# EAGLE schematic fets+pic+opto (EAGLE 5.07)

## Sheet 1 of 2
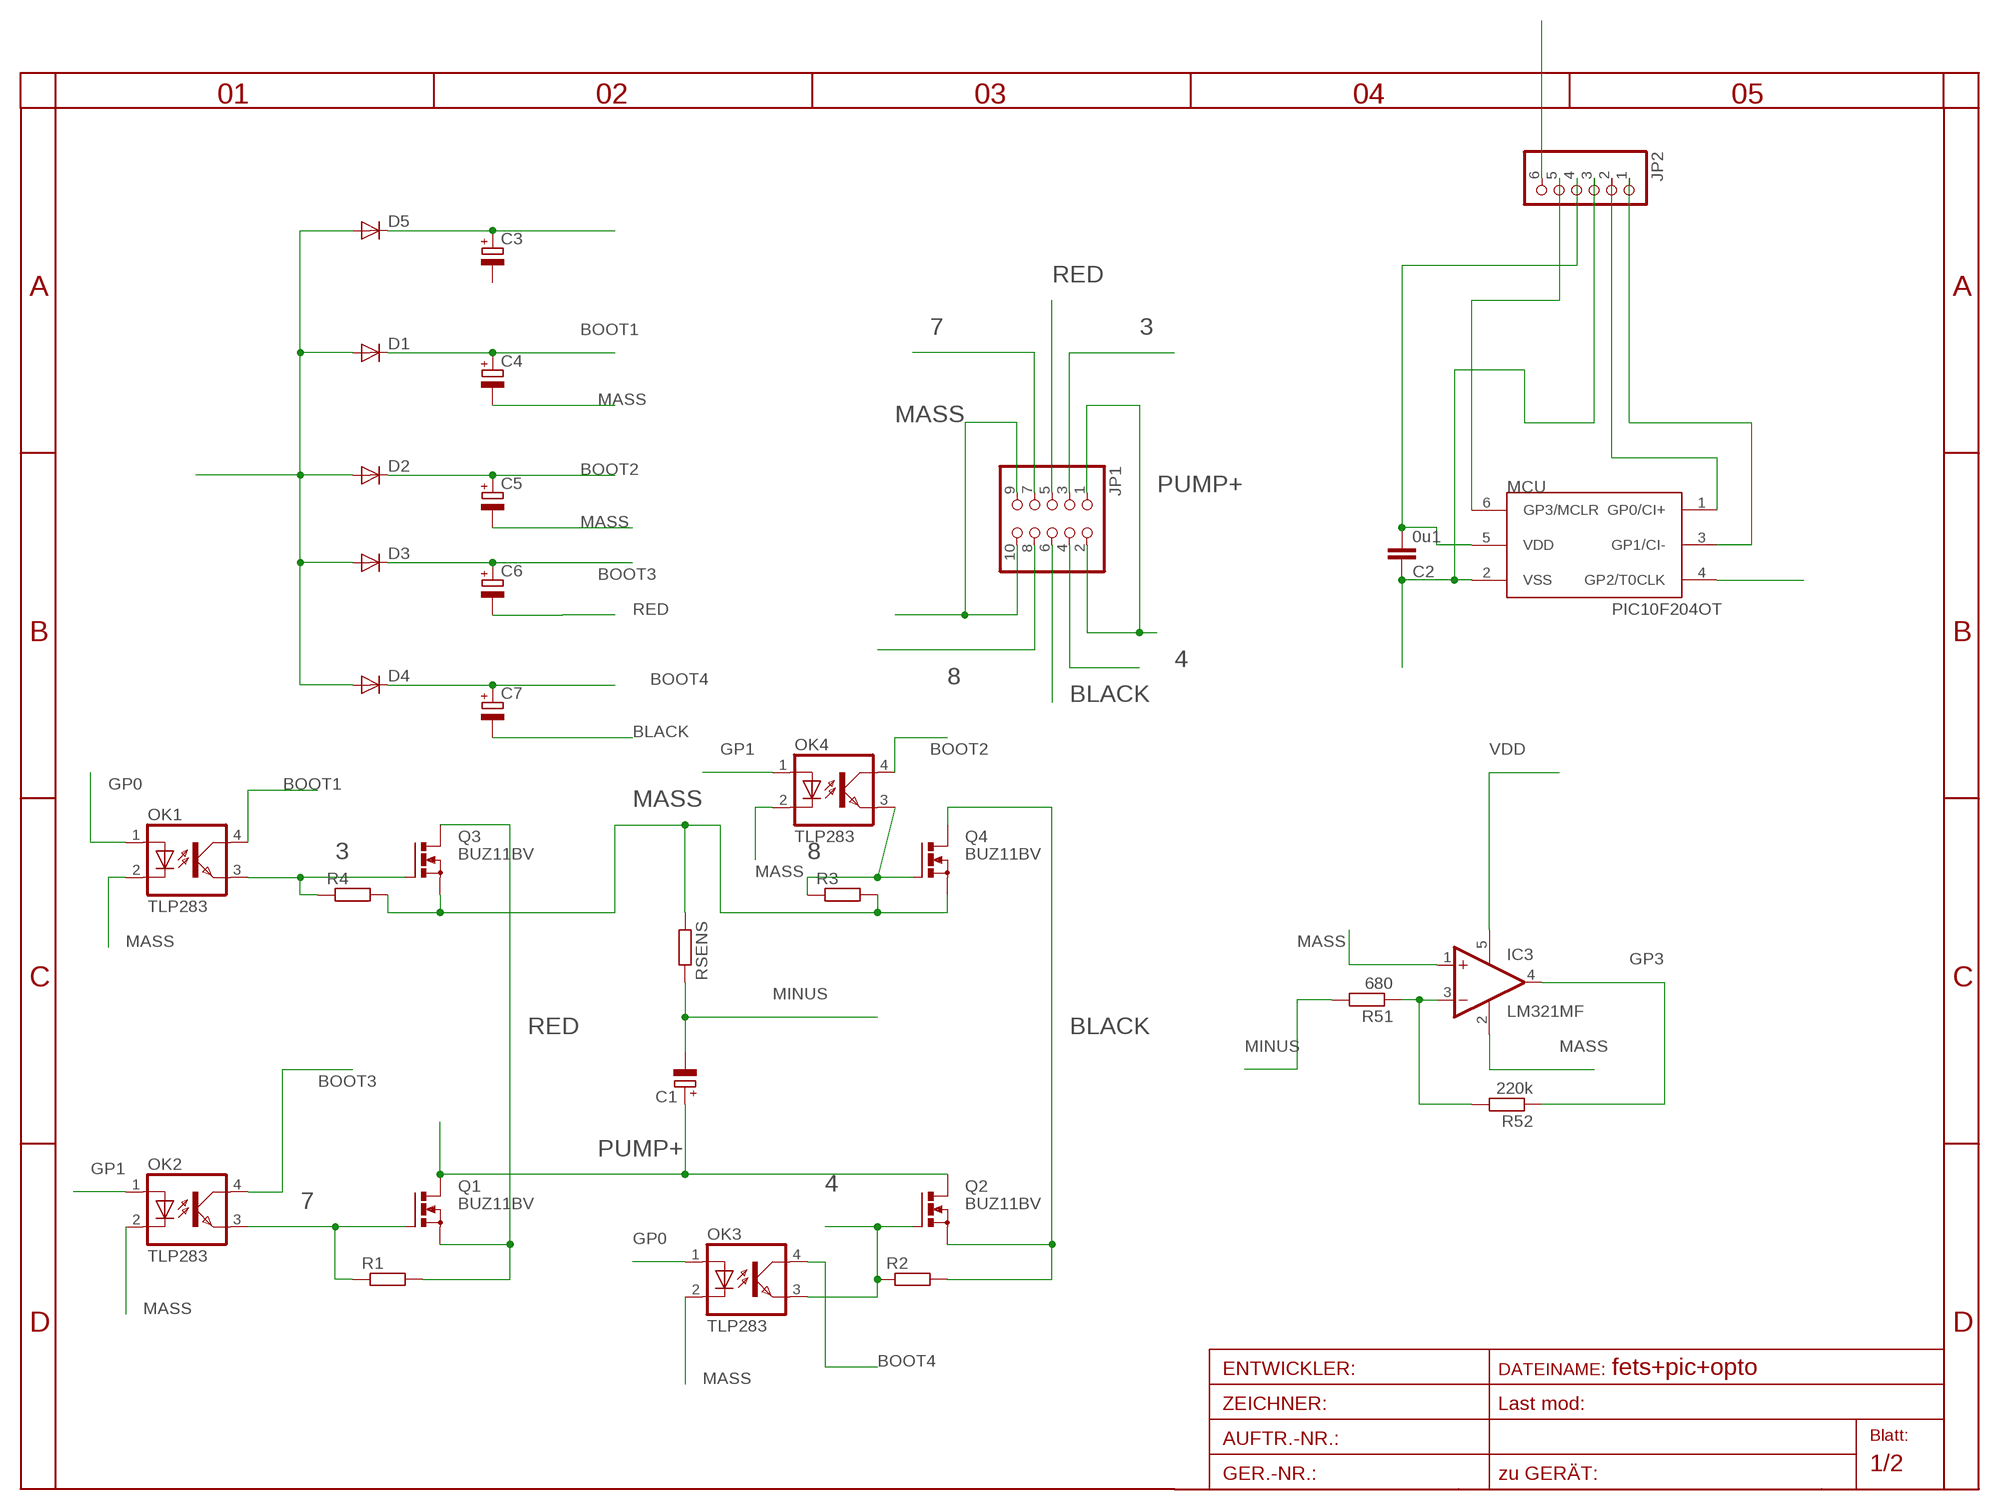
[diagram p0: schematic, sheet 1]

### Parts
C1  CPOL-EUE5-13  [E5-13]
C2  0u1  C-EUC1206  [C1206]
C3  CPOL-EUE2.5-7  [E2,5-7]
C4  CPOL-EUE2.5-7  [E2,5-7]
C5  CPOL-EUE2.5-7  [E2,5-7]
C6  CPOL-EUE2.5-7  [E2,5-7]
C7  CPOL-EUE2.5-7  [E2,5-7]
D1  DIODE-SMA-DO214  [SMA-DO214AC]
D2  DIODE-SMA-DO214  [SMA-DO214AC]
D3  DIODE-SMA-DO214  [SMA-DO214AC]
D4  DIODE-SMA-DO214  [SMA-DO214AC]
D5  DIODE-SMA-DO214  [SMA-DO214AC]
IC3  LM321MF  [SOT23-5]
JP1  PINHD-2X5  [2X05]
JP2  PINHD-1X6  [1X06BOX]
MCU  PIC10F204OT  [SOT23-6]
OK1  TLP283  [MINI-FLAT-4]
OK2  TLP283  [MINI-FLAT-4]
OK3  TLP283  [MINI-FLAT-4]
OK4  TLP283  [MINI-FLAT-4]
Q1  BUZ11BV  [TO220BV]
Q2  BUZ11BV  [TO220BV]
Q3  BUZ11BV  [TO220BV]
Q4  BUZ11BV  [TO220BV]
R1  R-EU_R1206  [R1206]
R2  R-EU_R1206  [R1206]
R3  R-EU_R1206  [R1206]
R4  R-EU_R1206  [R1206]
R51  680  R-EU_0207/10  [0207/10]
R52  220k  R-EU_0207/10  [0207/10]
RSENS  R-EU_0207/10  [0207/10]

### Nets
3: JP1.3 OK1.3(EMIT) Q3.G R4.1
4: JP1.4 OK3.3(EMIT) Q2.G R2.1
7: JP1.7 OK2.3(EMIT) Q1.G R1.1
8: JP1.8 OK4.3(EMIT) Q4.G R3.1
BATT+: JP2.6
BLACK: C7.- JP1.6 Q2.S Q4.D R2.2
BOOT1: C4.+ D1.K(C) OK1.4(COL)
BOOT2: C5.+ D2.K(C) OK4.4(COL)
BOOT3: C6.+ D3.K(C) OK2.4(COL)
BOOT4: C7.+ D4.K(C) OK3.4(COL)
GP0: JP2.2 MCU.1(GP0/CI+) OK1.1(A) OK3.1(A)
GP1: JP2.1 MCU.3(GP1/CI-) OK2.1(A) OK4.1(A)
GP2: MCU.4(GP2/T0CLK)
GP3: IC3.4(OUT) JP2.5 MCU.6(GP3/MCLR) R52.1
MASS: C2.1 C4.- C5.- IC3.1(+IN) IC3.2(V-) JP1.9 JP1.10 JP2.3 MCU.2(VSS) OK1.2(C) OK2.2(C) OK3.2(C) OK4.2(C) Q3.S Q4.S R3.2 R4.2 RSENS.1
MINUS: C1.- R51.2 RSENS.2
N$1: C3.+ D5.K(C)
N$3: D1.A D2.A D3.A D4.A D5.A
N$52: IC3.3(-IN) R51.1 R52.2
PUMP+: C1.+ JP1.1 JP1.2 Q1.D Q2.D
RED: C6.- JP1.5 Q1.S Q3.D R1.2
VDD: C2.2 IC3.5(V+) JP2.4 MCU.5(VDD)
Unconnected: C3.-

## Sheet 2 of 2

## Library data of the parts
C1 C3-C7 = rcl:CPOL-EU: POLARIZED CAPACITOR, European symbol
C2 = rcl:C-EU: CAPACITOR, European symbol
D1-D5 = diode:DIODE-: DIODE
IC3 = linear:LM321?*: Low Power Single Op Amp Source: http://cache.national.com/ds/LM/LM321.pdf
JP1 = pinhead:PINHD-2X5: PIN HEADER
JP2 = pinhead:PINHD-1X6: PIN HEADER
MCU = microchip-3:PIC10F2*: uPC nW 0,25/0,5k Program Flash memory Comparator
OK1-OK4 = optocoupler:TLP283: TOSHIBA PHOTOCOUPLER GaAs IRED & PHOTO-TRANSISTOR Source: http://www.semicon.toshiba.co.jp/td/en/Opto/Photocoupler/en_20050928_TLP283_datasheet.pdf
Q1-Q4 = transistor-power:BUZ11: N-CHANNEL MOS FET
R1-R4 R51 R52 RSENS = rcl:R-EU_: RESISTOR, European symbol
